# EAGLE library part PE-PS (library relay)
SLIM POWER Relay SOCKET NAiS Source: http://www.mew-europe.com/.. en_ds_61122_0000.pdf
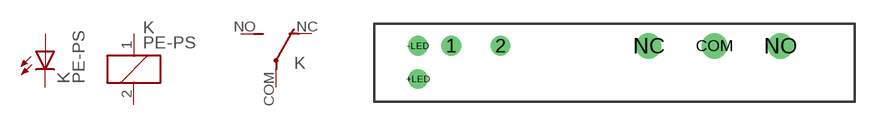
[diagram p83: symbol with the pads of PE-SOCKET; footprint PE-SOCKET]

Designator prefix K; gates 1=K 2=U -LED=LED

## PE-PS (OC_FARNELL: unknown; OC_NEWARK: unknown)  [PE-SOCKET]
1  1:1  pas
2  1:2  pas
+LED  -LED:A  pas
-LED  -LED:C  pas
COM  2:P  pas
NC  2:O  pas
NO  2:S  pas

## Footprint PE-SOCKET (pad centres in mm)
SLIM POWER Relay SOCKET NAiS Source: http://www.mew-europe.com/.. en_ds_61122_0000.pdf
drill 1 round: 1 -13.1,1.3; 2 -9.32,1.3; +LED -15.64,-1.24; -LED -15.64,1.3
drill 1.3 round: COM 7.06,1.3; NC 2.02,1.3; NO 12.1,1.3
